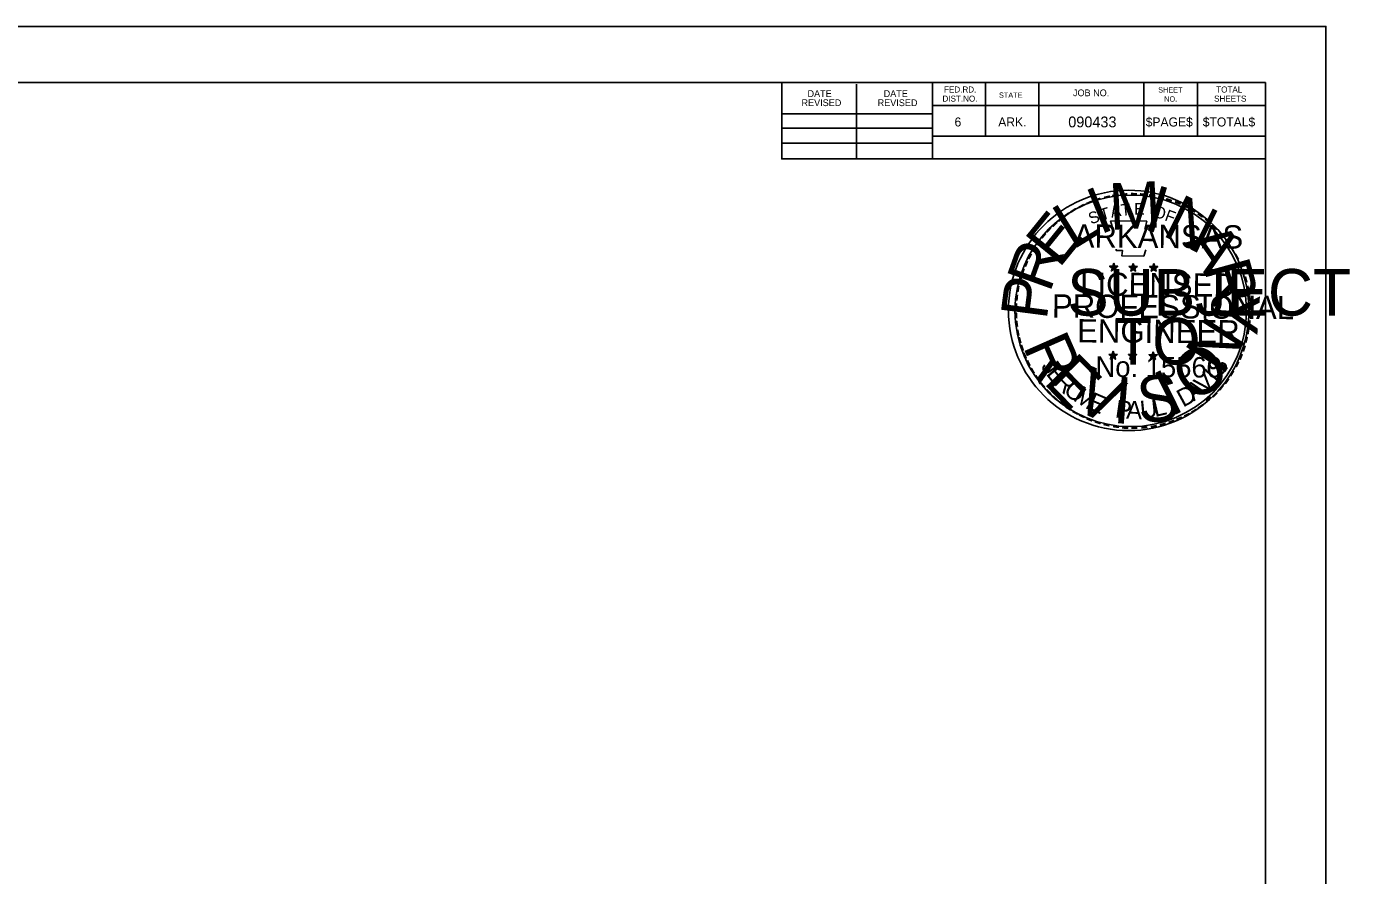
# Model space of a CAD drawing. Extents: x 0 to 34.3, y 0 to 22.
# Drawn here: x 17.17 to 34.31, y 11 to 22 of the extents above; entities that cross this region are included whole.
import ezdxf

# ---------------------------------------------------------------- set-up
doc = ezdxf.new("R2010")
doc.units = 0
for name, color, linetype in [('Level 1', 7, 'Continuous'), ('Level 49', 7, 'Continuous'), ('Level 62', 7, 'Continuous'), ('Level 63', 7, 'Continuous'), ('R_Border', 7, 'Continuous'), ('R_Border Prelim', 7, 'Continuous'), ('Stamp Mask', 7, 'Continuous')]:
    doc.layers.add(name, color=color, linetype=linetype)

msp = doc.modelspace()

# ---------------------------------------------------------------- linework, layer by layer
at = {"layer": 'Level 1'}
for p, q in [((1.597, 21.272), (33.215, 21.272)), ((26.951, 20.284), (26.951, 21.272)), ((27.919, 20.284), (27.919, 21.252)), ((28.905, 21.272), (28.905, 20.284)), ((29.589, 21.272), (29.589, 20.578)), ((30.283, 21.272), (30.283, 20.578)), ((31.641, 21.272), (31.641, 20.578)), ((32.335, 21.272), (32.335, 20.578)), ((33.215, 0.726), (33.215, 21.272)), ((33.215, 20.978), (28.905, 20.978)), ((33.215, 20.98), (33.215, 20.98)), ((26.951, 20.87), (28.905, 20.87)), ((26.951, 20.684), (28.905, 20.684)), ((33.215, 20.578), (28.905, 20.578)), ((29.201, 20.578), (33.215, 20.578)), ((26.951, 20.49), (28.905, 20.49)), ((33.215, 20.284), (26.951, 20.284))]:
    msp.add_line(p, q, dxfattribs=at)
msp.add_lwpolyline([(1.597, 21.272), (26.951, 21.272), (26.951, 20.284), (28.905, 20.284), (28.905, 20.284), (33.215, 20.284), (33.215, 9.02), (1.597, 9.02)], close=True, dxfattribs=at)
at = {"layer": 'Level 49'}
for p, q in [((31.198, 18.893), (31.252, 18.877)), ((31.198, 18.893), (31.237, 18.892)), ((31.198, 18.893), (31.237, 18.89)), ((31.198, 18.893), (31.233, 18.884)), ((31.198, 18.893), (31.233, 18.879)), ((31.198, 18.893), (31.233, 18.877)), ((31.198, 18.893), (31.233, 18.871)), ((31.22, 18.832), (31.252, 18.877)), ((31.22, 18.832), (31.233, 18.875)), ((31.22, 18.832), (31.237, 18.869)), ((31.22, 18.832), (31.239, 18.867)), ((31.22, 18.832), (31.245, 18.864)), ((31.22, 18.832), (31.252, 18.864)), ((31.22, 18.832), (31.252, 18.86)), ((31.252, 18.934), (31.245, 18.893)), ((31.252, 18.934), (31.245, 18.897)), ((31.252, 18.934), (31.248, 18.897)), ((31.252, 18.877), (31.252, 18.934)), ((31.252, 18.934), (31.261, 18.893)), ((31.252, 18.934), (31.259, 18.897)), ((31.252, 18.934), (31.254, 18.897)), ((31.304, 18.893), (31.252, 18.877)), ((31.284, 18.83), (31.252, 18.877)), ((31.284, 18.83), (31.252, 18.864)), ((31.284, 18.83), (31.252, 18.86)), ((31.304, 18.893), (31.256, 18.89)), ((31.284, 18.83), (31.256, 18.864)), ((31.304, 18.893), (31.261, 18.886)), ((31.304, 18.893), (31.261, 18.882)), ((31.284, 18.83), (31.261, 18.875)), ((31.284, 18.83), (31.261, 18.869)), ((31.284, 18.83), (31.267, 18.877)), ((31.304, 18.893), (31.269, 18.882)), ((31.304, 18.893), (31.274, 18.879)), ((31.304, 18.893), (31.276, 18.877)), ((31.449, 18.892), (31.503, 18.877)), ((31.449, 18.892), (31.488, 18.89)), ((31.449, 18.892), (31.488, 18.886)), ((31.449, 18.892), (31.488, 18.884)), ((31.449, 18.892), (31.486, 18.877)), ((31.449, 18.892), (31.486, 18.875)), ((31.449, 18.892), (31.486, 18.869)), ((31.472, 18.83), (31.503, 18.877)), ((31.472, 18.83), (31.488, 18.871)), ((31.472, 18.83), (31.488, 18.869)), ((31.472, 18.83), (31.49, 18.867)), ((31.472, 18.83), (31.496, 18.862)), ((31.472, 18.83), (31.503, 18.862)), ((31.472, 18.83), (31.503, 18.86)), ((31.503, 18.931), (31.496, 18.892)), ((31.503, 18.931), (31.496, 18.893)), ((31.503, 18.931), (31.498, 18.893)), ((31.503, 18.877), (31.503, 18.931)), ((31.503, 18.931), (31.512, 18.892)), ((31.503, 18.931), (31.511, 18.893)), ((31.503, 18.931), (31.505, 18.893)), ((31.555, 18.892), (31.503, 18.877)), ((31.535, 18.83), (31.503, 18.877)), ((31.535, 18.83), (31.503, 18.862)), ((31.535, 18.83), (31.503, 18.86)), ((31.555, 18.892), (31.509, 18.89)), ((31.535, 18.83), (31.509, 18.862)), ((31.555, 18.892), (31.512, 18.884)), ((31.555, 18.892), (31.512, 18.882)), ((31.535, 18.83), (31.512, 18.875)), ((31.535, 18.83), (31.512, 18.867)), ((31.535, 18.83), (31.518, 18.875)), ((31.555, 18.892), (31.52, 18.879)), ((31.555, 18.892), (31.525, 18.877)), ((31.555, 18.892), (31.527, 18.875)), ((31.715, 18.89), (31.769, 18.871)), ((31.715, 18.89), (31.758, 18.884)), ((31.715, 18.89), (31.754, 18.882)), ((31.715, 18.89), (31.754, 18.879)), ((31.715, 18.89), (31.753, 18.875)), ((31.715, 18.89), (31.753, 18.869)), ((31.715, 18.89), (31.753, 18.869)), ((31.736, 18.828), (31.769, 18.871)), ((31.736, 18.828), (31.754, 18.869)), ((31.736, 18.828), (31.758, 18.864)), ((31.736, 18.828), (31.758, 18.862)), ((31.736, 18.828), (31.769, 18.862)), ((31.736, 18.828), (31.766, 18.86)), ((31.736, 18.828), (31.773, 18.854)), ((31.769, 18.927), (31.76, 18.892)), ((31.769, 18.927), (31.766, 18.89)), ((31.769, 18.927), (31.766, 18.89)), ((31.769, 18.871), (31.769, 18.927)), ((31.769, 18.927), (31.78, 18.89)), ((31.769, 18.927), (31.777, 18.89)), ((31.769, 18.927), (31.773, 18.89)), ((31.821, 18.89), (31.769, 18.871)), ((31.799, 18.828), (31.769, 18.871)), ((31.799, 18.828), (31.769, 18.862)), ((31.799, 18.828), (31.769, 18.854)), ((31.821, 18.89), (31.775, 18.884)), ((31.799, 18.828), (31.775, 18.86)), ((31.821, 18.89), (31.78, 18.882)), ((31.821, 18.89), (31.78, 18.877)), ((31.799, 18.828), (31.78, 18.869)), ((31.799, 18.828), (31.78, 18.864)), ((31.799, 18.828), (31.784, 18.869)), ((31.821, 18.89), (31.788, 18.875)), ((31.821, 18.89), (31.79, 18.875)), ((31.821, 18.89), (31.795, 18.871)), ((31.191, 17.751), (31.245, 17.734)), ((31.191, 17.751), (31.23, 17.749)), ((31.191, 17.751), (31.228, 17.743)), ((31.191, 17.751), (31.228, 17.743)), ((31.191, 17.751), (31.228, 17.736)), ((31.191, 17.751), (31.228, 17.734)), ((31.191, 17.751), (31.228, 17.732)), ((31.209, 17.693), (31.245, 17.734)), ((31.209, 17.693), (31.228, 17.734)), ((31.209, 17.693), (31.23, 17.727)), ((31.209, 17.693), (31.231, 17.727)), ((31.209, 17.693), (31.245, 17.725)), ((31.209, 17.693), (31.237, 17.721)), ((31.209, 17.693), (31.245, 17.719)), ((31.245, 17.792), (31.233, 17.755)), ((31.245, 17.792), (31.237, 17.751)), ((31.245, 17.792), (31.239, 17.751)), ((31.274, 17.689), (31.241, 17.719)), ((31.245, 17.734), (31.245, 17.792)), ((31.245, 17.792), (31.252, 17.751)), ((31.245, 17.792), (31.252, 17.751)), ((31.245, 17.792), (31.245, 17.751)), ((31.297, 17.751), (31.245, 17.734)), ((31.274, 17.689), (31.245, 17.734)), ((31.274, 17.689), (31.245, 17.721)), ((31.274, 17.689), (31.246, 17.721)), ((31.297, 17.751), (31.248, 17.749)), ((31.297, 17.751), (31.252, 17.743)), ((31.297, 17.751), (31.252, 17.741)), ((31.274, 17.689), (31.252, 17.734)), ((31.274, 17.689), (31.252, 17.727)), ((31.297, 17.751), (31.259, 17.74)), ((31.274, 17.689), (31.259, 17.734)), ((31.297, 17.751), (31.263, 17.736)), ((31.297, 17.751), (31.267, 17.734)), ((31.442, 17.751), (31.496, 17.734)), ((31.442, 17.751), (31.481, 17.747)), ((31.442, 17.751), (31.481, 17.743)), ((31.442, 17.751), (31.481, 17.741)), ((31.442, 17.751), (31.479, 17.736)), ((31.442, 17.751), (31.479, 17.732)), ((31.442, 17.751), (31.479, 17.728)), ((31.46, 17.689), (31.496, 17.734)), ((31.46, 17.689), (31.481, 17.732)), ((31.46, 17.689), (31.481, 17.725)), ((31.46, 17.689), (31.483, 17.725)), ((31.46, 17.689), (31.488, 17.721)), ((31.46, 17.689), (31.496, 17.721)), ((31.46, 17.689), (31.496, 17.717)), ((31.496, 17.788), (31.486, 17.751)), ((31.496, 17.788), (31.488, 17.751)), ((31.496, 17.788), (31.49, 17.751)), ((31.525, 17.689), (31.494, 17.717)), ((31.496, 17.734), (31.496, 17.788)), ((31.496, 17.788), (31.503, 17.749)), ((31.496, 17.788), (31.503, 17.749)), ((31.496, 17.788), (31.496, 17.751)), ((31.546, 17.749), (31.496, 17.734)), ((31.525, 17.689), (31.496, 17.734)), ((31.525, 17.689), (31.496, 17.721)), ((31.525, 17.689), (31.498, 17.721)), ((31.546, 17.749), (31.501, 17.749)), ((31.546, 17.749), (31.503, 17.741)), ((31.546, 17.749), (31.503, 17.741)), ((31.525, 17.689), (31.503, 17.732)), ((31.525, 17.689), (31.503, 17.727)), ((31.546, 17.749), (31.511, 17.736)), ((31.525, 17.689), (31.511, 17.732)), ((31.546, 17.749), (31.516, 17.734)), ((31.546, 17.749), (31.518, 17.732)), ((31.708, 17.747), (31.762, 17.728)), ((31.708, 17.747), (31.747, 17.743)), ((31.708, 17.747), (31.747, 17.74)), ((31.708, 17.747), (31.745, 17.736)), ((31.708, 17.747), (31.745, 17.732)), ((31.708, 17.747), (31.743, 17.728)), ((31.708, 17.747), (31.743, 17.725)), ((31.728, 17.686), (31.762, 17.728)), ((31.728, 17.686), (31.745, 17.728)), ((31.728, 17.686), (31.747, 17.721)), ((31.728, 17.686), (31.751, 17.721)), ((31.728, 17.686), (31.754, 17.717)), ((31.728, 17.686), (31.76, 17.717)), ((31.728, 17.686), (31.762, 17.714)), ((31.762, 17.786), (31.753, 17.747)), ((31.762, 17.786), (31.754, 17.747)), ((31.762, 17.786), (31.758, 17.747)), ((31.792, 17.686), (31.76, 17.717)), ((31.792, 17.686), (31.76, 17.714)), ((31.762, 17.728), (31.762, 17.786)), ((31.762, 17.786), (31.769, 17.747)), ((31.762, 17.786), (31.769, 17.747)), ((31.762, 17.786), (31.762, 17.747)), ((31.814, 17.747), (31.762, 17.728)), ((31.792, 17.686), (31.762, 17.728)), ((31.792, 17.686), (31.766, 17.717)), ((31.814, 17.747), (31.767, 17.743)), ((31.814, 17.747), (31.769, 17.74)), ((31.814, 17.747), (31.769, 17.736)), ((31.792, 17.686), (31.769, 17.721)), ((31.792, 17.686), (31.773, 17.728)), ((31.792, 17.686), (31.775, 17.728)), ((31.814, 17.747), (31.78, 17.734)), ((31.814, 17.747), (31.782, 17.728)), ((31.814, 17.747), (31.784, 17.728))]:
    msp.add_line(p, q, dxfattribs=at)
for points in [[(31.209, 19.48), (31.246, 19.353)], [(31.738, 19.336), (31.76, 19.381), (31.654, 19.375), (31.678, 19.476), (31.209, 19.48)], [(31.282, 19.113), (31.282, 19.098), (31.365, 19.096), (31.358, 19.027), (31.639, 19.026), (31.669, 19.104)], [(31.252, 18.934), (31.284, 18.83), (31.198, 18.893), (31.304, 18.893), (31.22, 18.832), (31.252, 18.934)], [(31.503, 18.931), (31.535, 18.83), (31.449, 18.892), (31.555, 18.892), (31.472, 18.83), (31.503, 18.931)], [(31.769, 18.927), (31.799, 18.828), (31.715, 18.89), (31.821, 18.89), (31.736, 18.828), (31.769, 18.927)], [(31.245, 17.792), (31.274, 17.689), (31.191, 17.751), (31.297, 17.751), (31.209, 17.693), (31.245, 17.792)], [(31.496, 17.788), (31.525, 17.689), (31.442, 17.751), (31.546, 17.749), (31.46, 17.689), (31.496, 17.788)], [(31.762, 17.786), (31.792, 17.686), (31.708, 17.747), (31.814, 17.747), (31.728, 17.686), (31.762, 17.786)], [(32.46, 17.142), (32.452, 17.166), (32.497, 17.204)], [(32.493, 17.209), (32.501, 17.187), (32.456, 17.148)], [(32.501, 17.191), (32.456, 17.152)], [(32.501, 17.187), (32.458, 17.15)]]:
    msp.add_lwpolyline(points, dxfattribs=at)
for centre, radius in [((31.253, 18.876), 0.026), ((31.253, 18.876), 0.0235), ((31.253, 18.876), 0.0218), ((31.253, 18.876), 0.02), ((31.253, 18.876), 0.0175), ((31.253, 18.876), 0.0162), ((31.253, 18.876), 0.0149), ((31.253, 18.876), 0.0129), ((31.253, 18.876), 0.0113), ((31.253, 18.876), 0.00937), ((31.253, 18.876), 0.00747), ((31.253, 18.876), 0.00557), ((31.253, 18.876), 0.00447), ((31.253, 18.876), 0.00217), ((31.505, 18.874), 0.026), ((31.505, 18.874), 0.0235), ((31.505, 18.874), 0.0218), ((31.505, 18.874), 0.02), ((31.505, 18.874), 0.0175), ((31.505, 18.874), 0.0162), ((31.505, 18.874), 0.0149), ((31.505, 18.874), 0.0129), ((31.505, 18.874), 0.0113), ((31.505, 18.874), 0.00937), ((31.505, 18.874), 0.00747), ((31.505, 18.874), 0.00557), ((31.505, 18.874), 0.00447), ((31.505, 18.874), 0.00217), ((31.771, 18.87), 0.026), ((31.771, 18.87), 0.0235), ((31.771, 18.87), 0.0218), ((31.771, 18.87), 0.02), ((31.771, 18.87), 0.0175), ((31.771, 18.87), 0.0162), ((31.771, 18.87), 0.0149), ((31.771, 18.87), 0.0129), ((31.771, 18.87), 0.0113), ((31.771, 18.87), 0.00937), ((31.771, 18.87), 0.00747), ((31.771, 18.87), 0.00557), ((31.771, 18.87), 0.00447), ((31.771, 18.87), 0.00217), ((31.244, 17.734), 0.026), ((31.244, 17.734), 0.0235), ((31.244, 17.734), 0.0218), ((31.244, 17.734), 0.02), ((31.244, 17.734), 0.0175), ((31.244, 17.734), 0.0162), ((31.244, 17.734), 0.0149), ((31.244, 17.734), 0.0129), ((31.244, 17.734), 0.0113), ((31.244, 17.734), 0.00937), ((31.244, 17.734), 0.00747), ((31.244, 17.734), 0.00557), ((31.244, 17.734), 0.00447), ((31.244, 17.734), 0.00217), ((31.496, 17.732), 0.026), ((31.496, 17.732), 0.0235), ((31.496, 17.732), 0.0218), ((31.496, 17.732), 0.02), ((31.496, 17.732), 0.0175), ((31.496, 17.732), 0.0162), ((31.496, 17.732), 0.0149), ((31.496, 17.732), 0.0129), ((31.496, 17.732), 0.0113), ((31.496, 17.732), 0.00937), ((31.496, 17.732), 0.00747), ((31.496, 17.732), 0.00557), ((31.496, 17.732), 0.00447), ((31.496, 17.732), 0.00217), ((31.762, 17.729), 0.026), ((31.762, 17.729), 0.0235), ((31.762, 17.729), 0.0218), ((31.762, 17.729), 0.02), ((31.762, 17.729), 0.0175), ((31.762, 17.729), 0.0162), ((31.762, 17.729), 0.0149), ((31.762, 17.729), 0.0129), ((31.762, 17.729), 0.0113), ((31.762, 17.729), 0.00937), ((31.762, 17.729), 0.00747), ((31.762, 17.729), 0.00557), ((31.762, 17.729), 0.00447), ((31.762, 17.729), 0.00217)]:
    msp.add_circle(centre, radius, dxfattribs=at)
at = {"layer": 'Level 62'}
msp.add_lwpolyline([(1.597, 21.272), (26.951, 21.272), (26.951, 21.272), (26.951, 20.284), (26.951, 20.284), (28.585, 20.284), (28.905, 20.284), (28.905, 20.284), (28.905, 20.284), (33.215, 20.284), (33.215, 9.02), (1.597, 9.02)], close=True, dxfattribs=at)
at = {"layer": 'Level 63'}
msp.add_lwpolyline([(0, 0), (34, 0), (34, 22), (0, 22)], close=True, dxfattribs=at)
at = {"layer": 'R_Border Prelim'}
msp.add_circle((31.472, 18.316), 1.5, dxfattribs=at)
at = {"layer": 'Stamp Mask'}
msp.add_circle((31.445, 18.321), 1.557, dxfattribs=at)

# ---------------------------------------------------------------- texts
at = {"layer": 'Level 1'}
for s, height, p in [('DATE', 0.0879, (27.285, 21.086)), ('DATE', 0.0879, (28.271, 21.086)), ('DIST.NO.', 0.0782, (29.033, 21.026)), ('FED.RD.', 0.0782, (29.053, 21.144)), ('STATE', 0.0684, (29.765, 21.076)), ('SHEET', 0.0684, (31.827, 21.144)), ('NO.', 0.0684, (31.905, 21.026)), ('SHEETS', 0.0782, (32.551, 21.026)), ('TOTAL', 0.0782, (32.579, 21.144)), ('REVISED', 0.0879, (27.207, 20.968)), ('REVISED', 0.0879, (28.193, 20.968)), ('6', 0.117, (29.189, 20.704)), ('ARK.', 0.1172, (29.755, 20.704)), ('090433', 0.14, (30.662, 20.693)), ('$PAGE$', 0.1172, (31.665, 20.704)), ('$TOTAL$', 0.1172, (32.404, 20.704))]:
    msp.add_text(s, height=height, dxfattribs=at).set_placement(p)
at = {"layer": 'Level 49'}
for s, height, rotation, p in [('-', 0.241, 23.9096, (30.923, 19.612)), ('-', 0.241, 18.7785, (31.019, 19.653)), ('-', 0.241, 13.2326, (31.133, 19.688)), ('-', 0.241, 9.8217, (31.233, 19.712)), ('-', 0.241, 5.4992, (31.345, 19.727)), ('-', 0.241, 359.7886, (31.46, 19.738)), ('E', 0.151, 0.4347, (31.516, 19.56)), ('-', 0.241, 357.3454, (31.572, 19.735)), ('-', 0.241, 351.7641, (31.682, 19.725)), ('-', 0.241, 346.8073, (31.792, 19.708)), ('-', 0.241, 341.9386, (31.887, 19.682)), ('-', 0.241, 337.4575, (31.996, 19.649)), ('-', 0.241, 35.8341, (30.649, 19.452)), ('-', 0.241, 33.666, (30.736, 19.511)), ('-', 0.241, 28.3942, (30.828, 19.565)), ('S', 0.151, 21.1964, (30.958, 19.433)), ('T', 0.151, 16.006, (31.096, 19.483)), ('A', 0.151, 10.8156, (31.222, 19.521)), ('T', 0.151, 5.6252, (31.351, 19.545)), ('O', 0.151, 350.0539, (31.758, 19.528)), ('F', 0.151, 339.6731, (31.901, 19.491)), ('-', 0.241, 333.7235, (32.093, 19.61)), ('-', 0.241, 329.2433, (32.179, 19.565)), ('-', 0.241, 325.4651, (32.275, 19.507)), ('-', 0.241, 48.0254, (30.442, 19.262)), ('-', 0.241, 42.5646, (30.511, 19.333)), ('-', 0.241, 38.5531, (30.578, 19.394)), ('ARKANSAS', 0.3015, 359.6024, (30.731, 19.137)), ('-', 0.241, 320.1321, (32.367, 19.444)), ('-', 0.241, 315.181, (32.458, 19.37)), ('-', 0.241, 53.8349, (30.318, 19.104)), ('-', 0.241, 50.2166, (30.381, 19.189)), ('-', 0.241, 309.4821, (32.542, 19.286)), ('-', 0.241, 306.2546, (32.618, 19.195)), ('-', 0.241, 62.4738, (30.223, 18.931)), ('-', 0.241, 57.673, (30.269, 19.022)), ('-', 0.211, 303.2777, (32.692, 19.107)), ('-', 0.241, 299.2708, (32.739, 19.016)), ('-', 0.241, 71.9969, (30.148, 18.745)), ('-', 0.241, 67.3767, (30.184, 18.839)), ('-', 0.241, 294.2652, (32.787, 18.923)), ('-', 0.241, 290.1752, (32.828, 18.839)), ('-', 0.241, 75.0634, (30.119, 18.637)), ('LICENSED', 0.3015, 359.6024, (30.815, 18.512)), ('-', 0.241, 284.7257, (32.86, 18.75)), ('-', 0.241, 84.7887, (30.085, 18.426)), ('-', 0.241, 80.8037, (30.096, 18.531)), ('PROFESSIONAL', 0.30153, 359.6024, (30.45, 18.229)), ('-', 0.241, 280.1517, (32.89, 18.637)), ('-', 0.241, 276.1986, (32.916, 18.521)), ('-', 0.241, 88.6646, (30.081, 18.32)), ('-', 0.241, 273.9325, (32.923, 18.411)), ('-', 0.241, 93.7983, (30.085, 18.21)), ('-', 0.241, 98.5503, (30.096, 18.108)), ('ENGINEER', 0.3015, 359.6024, (30.776, 17.907)), ('-', 0.241, 263.1196, (32.923, 18.218)), ('-', 0.241, 269.5431, (32.927, 18.318)), ('-', 0.241, 101.3173, (30.113, 17.998)), ('-', 0.241, 260.5977, (32.91, 18.119)), ('-', 0.241, 105.0602, (30.139, 17.909)), ('-', 0.241, 108.6898, (30.171, 17.816)), ('-', 0.241, 252.4705, (32.867, 17.907)), ('-', 0.241, 255.365, (32.893, 18.017)), ('-', 0.241, 113.6667, (30.208, 17.723)), ('-', 0.241, 115.3313, (30.255, 17.63)), ('J', 0.232, 303.9209, (30.3, 17.594)), ('No. 15560', 0.2653, 359.6024, (31.014, 17.461)), ('S', 0.232, 53.5227, (32.631, 17.446)), ('-', 0.241, 244.2221, (32.791, 17.712)), ('-', 0.241, 247.4911, (32.834, 17.805)), ('-', 0.241, 120.0495, (30.307, 17.541)), ('-', 0.241, 125.4958, (30.368, 17.457)), ('E', 0.232, 308.618, (30.366, 17.497)), ('R', 0.232, 314.7784, (30.463, 17.378)), ('V', 0.232, 41.4844, (32.42, 17.234)), ('I', 0.232, 49.9999, (32.574, 17.38)), ('-', 0.241, 238.6736, (32.731, 17.6)), ('-', 0.241, 130.3205, (30.435, 17.373)), ('O', 0.232, 321.6761, (30.587, 17.259)), ('M', 0.232, 328.1357, (30.714, 17.161)), ('D', 0.232, 28.5809, (32.149, 17.061)), ('A', 0.232, 34.8903, (32.286, 17.138)), ('-', 0.241, 233.4476, (32.603, 17.42)), ('-', 0.241, 233.4476, (32.674, 17.501)), ('-', 0.241, 133.8262, (30.513, 17.291)), ('-', 0.241, 138.5362, (30.589, 17.22)), ('-', 0.241, 144.2487, (30.677, 17.159)), ('E', 0.232, 336.4966, (30.895, 17.056)), ('P', 0.232, 351.9783, (31.261, 16.937)), ('A', 0.232, 357.9896, (31.409, 16.918)), ('U', 0.232, 5.7635, (31.603, 16.916)), ('L', 0.232, 13.0992, (31.784, 16.939)), ('-', 0.241, 225.3677, (32.532, 17.332)), ('-', 0.241, 147.6922, (30.759, 17.101)), ('-', 0.241, 151.1728, (30.844, 17.053)), ('-', 0.241, 154.2026, (30.926, 17.014)), ('-', 0.241, 206.9592, (32.205, 17.075)), ('-', 0.241, 211.8515, (32.288, 17.127)), ('-', 0.241, 215.3387, (32.368, 17.185)), ('-', 0.241, 158.1636, (31.019, 16.973)), ('-', 0.241, 162.4007, (31.124, 16.941)), ('-', 0.241, 167.1579, (31.23, 16.917)), ('-', 0.241, 172.7179, (31.345, 16.9)), ('-', 0.241, 176.1207, (31.459, 16.889)), ('-', 0.241, 181.1942, (31.57, 16.893)), ('-', 0.241, 185.4191, (31.693, 16.902)), ('-', 0.241, 190.8882, (31.805, 16.921)), ('-', 0.241, 195.0767, (31.914, 16.951)), ('-', 0.241, 200.3208, (32.017, 16.988)), ('-', 0.241, 203.854, (32.11, 17.029))]:
    msp.add_text(s, height=height, rotation=rotation, dxfattribs=at).set_placement(p)
at = {"layer": 'R_Border'}
msp.add_text('JOB NO.', height=0.0879, dxfattribs=at).set_placement((30.723, 21.096))
msp.add_text('JOB NO.', height=0.0879, dxfattribs=at).set_placement((30.723, 21.096))
at = {"layer": 'R_Border Prelim'}
for s, rotation, p in [('I', 22.0105, (31.07, 19.298)), ('M', 2.6943, (31.203, 19.364)), ('I', 343.3781, (31.625, 19.376)), ('N', 333.7199, (31.864, 19.299)), ('E', 50.9849, (30.542, 18.857)), ('L', 31.6686, (30.72, 19.1)), ('R', 70.3011, (30.422, 18.539)), ('A', 304.7456, (32.147, 19.195)), ('R', 285.4294, (32.41, 18.889)), ('P', 82.6089, (30.382, 18.187)), ('Y', 266.1131, (32.545, 18.563)), ('N', 57.1378, (32.66, 17.465)), ('R', 293.7639, (30.069, 17.857)), ('O', 36.5754, (32.295, 17.107)), ('E', 314.3262, (30.328, 17.386)), ('V', 334.8885, (30.702, 17.059)), ('S', 5.732, (31.583, 16.855)), ('I', 26.2943, (31.987, 16.938)), ('I', 355.4508, (31.233, 16.866))]:
    msp.add_text(s, height=0.603, rotation=rotation, dxfattribs=at).set_placement(p)
for s, p in [('SUBJECT', (30.648, 18.254)), ('TO', (31.257, 17.62))]:
    msp.add_text(s, height=0.6034, dxfattribs=at).set_placement(p)

doc.saveas('drawing.dxf')
